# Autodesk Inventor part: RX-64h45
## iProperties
Created: 2009-01
Part Number: RX-64h45
Material: Aluminum-6061
Document SubType Name: Sheet Metal
Designer: Administrator
Density: 1 g/cm^3
Author: Administrator
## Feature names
1. Hole1
2. Hole2
3. Corner Round2
4. Plate1
5. Plate2
6. Bend1
7. Cut1
8. Cut5
9. Cut6
10. Cut7
